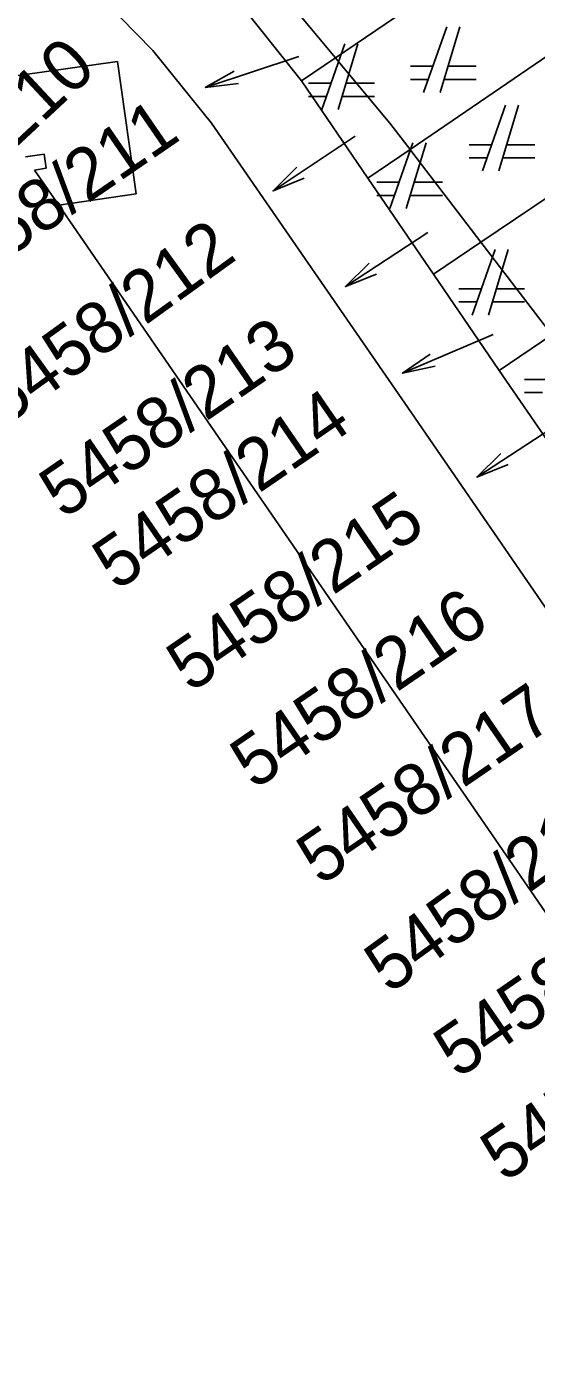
# Model space of a CAD drawing. Extents: x -263587 to -261993, y -1238795 to -1236748.
# Drawn here: x -262822.15 to -262811.29, y -1237202.79 to -1237174.42 of the extents above; entities that cross this region are included whole.
import ezdxf

# ---------------------------------------------------------------- set-up
doc = ezdxf.new("R2010")
doc.units = 0
doc.layers.add('Vrstva 1', color=7, linetype='Continuous')

msp = doc.modelspace()

# ---------------------------------------------------------------- linework, layer by layer
at = {"layer": 'Vrstva 1'}
for p, q in [((-262812.15, -1237172.77), (-262815.57, -1237175.09)), ((-262815.57, -1237175.09), (-262812.15, -1237172.77)), ((-262815.57, -1237175.09), (-262817.11, -1237173.24)), ((-262817.11, -1237173.24), (-262815.57, -1237175.09)), ((-262817.79, -1237173.7), (-262816.29, -1237175.58)), ((-262816.29, -1237175.58), (-262817.79, -1237173.7)), ((-262819.46, -1237174.93), (-262820.51, -1237173.86)), ((-262820.51, -1237173.86), (-262819.46, -1237174.93)), ((-262813.2, -1237174.43), (-262813.69, -1237175.83)), ((-262813.34, -1237175.83), (-262812.92, -1237174.43)), ((-262815.37, -1237174.79), (-262815.86, -1237176.19)), ((-262815.51, -1237176.19), (-262815.09, -1237174.79)), ((-262810.73, -1237174.83), (-262813.98, -1237177.04)), ((-262813.98, -1237177.04), (-262810.73, -1237174.83)), ((-262818.21, -1237176.48), (-262819.46, -1237174.93)), ((-262819.46, -1237174.93), (-262818.21, -1237176.48)), ((-262816.29, -1237175.58), (-262815.57, -1237175.09)), ((-262815.57, -1237175.09), (-262816.29, -1237175.58)), ((-262815.52, -1237175.15), (-262815.57, -1237175.09)), ((-262815.57, -1237175.09), (-262815.52, -1237175.15)), ((-262823.26, -1237175.6), (-262820.21, -1237175.17)), ((-262820.21, -1237175.17), (-262823.26, -1237175.6)), ((-262820.21, -1237175.17), (-262819.81, -1237177.99)), ((-262819.81, -1237177.99), (-262820.21, -1237175.17)), ((-262814.41, -1237176.48), (-262815.52, -1237175.15)), ((-262815.52, -1237175.15), (-262814.41, -1237176.48)), ((-262813.494, -1237175.27), (-262813.97, -1237175.27)), ((-262812.57, -1237175.27), (-262813.172, -1237175.27)), ((-262817.634, -1237175.636), (-262818.342, -1237175.725)), ((-262816.29, -1237175.58), (-262814.88, -1237177.65)), ((-262814.88, -1237177.65), (-262816.29, -1237175.58)), ((-262815.664, -1237175.63), (-262816.14, -1237175.63)), ((-262814.74, -1237175.63), (-262815.342, -1237175.63)), ((-262813.97, -1237175.55), (-262813.592, -1237175.55)), ((-262813.256, -1237175.55), (-262812.57, -1237175.55)), ((-262816.14, -1237175.91), (-262815.762, -1237175.91)), ((-262815.426, -1237175.91), (-262814.74, -1237175.91)), ((-262811.95, -1237176.1), (-262812.44, -1237177.5)), ((-262812.09, -1237177.5), (-262811.67, -1237176.1)), ((-262813.95, -1237182.65), (-262818.21, -1237176.48)), ((-262818.21, -1237176.48), (-262813.95, -1237182.65)), ((-262813.98, -1237177.04), (-262814.41, -1237176.48)), ((-262814.41, -1237176.48), (-262813.98, -1237177.04)), ((-262814.88, -1237177.65), (-262813.98, -1237177.04)), ((-262813.98, -1237177.04), (-262814.88, -1237177.65)), ((-262813.92, -1237176.9), (-262814.41, -1237178.3)), ((-262814.06, -1237178.3), (-262813.64, -1237176.9)), ((-262813.94, -1237177.09), (-262813.98, -1237177.04)), ((-262813.98, -1237177.04), (-262813.94, -1237177.09)), ((-262812.47, -1237179.02), (-262813.94, -1237177.09)), ((-262813.94, -1237177.09), (-262812.47, -1237179.02)), ((-262812.244, -1237176.94), (-262812.72, -1237176.94)), ((-262809.32, -1237176.88), (-262812.47, -1237179.02)), ((-262812.47, -1237179.02), (-262809.32, -1237176.88)), ((-262811.32, -1237176.94), (-262811.922, -1237176.94)), ((-262822.17, -1237177.2), (-262821.77, -1237177.14)), ((-262821.77, -1237177.14), (-262821.73, -1237177.44)), ((-262812.72, -1237177.22), (-262812.342, -1237177.22)), ((-262812.006, -1237177.22), (-262811.32, -1237177.22)), ((-262821.73, -1237177.44), (-262821.98, -1237177.48)), ((-262821.98, -1237177.48), (-262821.46, -1237178.23)), ((-262816.237, -1237177.653), (-262816.897, -1237177.925)), ((-262814.88, -1237177.65), (-262813.48, -1237179.7)), ((-262813.48, -1237179.7), (-262814.88, -1237177.65)), ((-262814.214, -1237177.74), (-262814.69, -1237177.74)), ((-262813.29, -1237177.74), (-262813.892, -1237177.74)), ((-262819.81, -1237177.99), (-262821.46, -1237178.23)), ((-262821.46, -1237178.23), (-262819.81, -1237177.99)), ((-262821.46, -1237178.23), (-262797.76, -1237212.68)), ((-262797.76, -1237212.68), (-262821.46, -1237178.23)), ((-262814.69, -1237178.02), (-262814.312, -1237178.02)), ((-262813.976, -1237178.02), (-262813.29, -1237178.02)), ((-262813.48, -1237179.7), (-262812.47, -1237179.02)), ((-262812.47, -1237179.02), (-262813.48, -1237179.7)), ((-262812.42, -1237179.08), (-262812.47, -1237179.02)), ((-262812.47, -1237179.02), (-262812.42, -1237179.08)), ((-262810.96, -1237180.99), (-262812.42, -1237179.08)), ((-262812.42, -1237179.08), (-262810.96, -1237180.99)), ((-262812.17, -1237179.17), (-262812.66, -1237180.57)), ((-262812.31, -1237180.57), (-262811.89, -1237179.17)), ((-262814.693, -1237179.696), (-262815.355, -1237179.963)), ((-262813.48, -1237179.7), (-262812.08, -1237181.75)), ((-262812.08, -1237181.75), (-262813.48, -1237179.7)), ((-262812.464, -1237180.01), (-262812.94, -1237180.01)), ((-262811.54, -1237180.01), (-262812.142, -1237180.01)), ((-262812.94, -1237180.29), (-262812.562, -1237180.29)), ((-262812.226, -1237180.29), (-262811.54, -1237180.29)), ((-262812.08, -1237181.75), (-262810.96, -1237180.99)), ((-262810.96, -1237180.99), (-262812.08, -1237181.75)), ((-262813.442, -1237181.659), (-262814.141, -1237181.806)), ((-262812.08, -1237181.75), (-262810.67, -1237183.8)), ((-262810.67, -1237183.8), (-262812.08, -1237181.75)), ((-262811.064, -1237181.94), (-262811.54, -1237181.94)), ((-262811.54, -1237182.22), (-262811.162, -1237182.22)), ((-262808, -1237191.31), (-262813.95, -1237182.65)), ((-262813.95, -1237182.65), (-262808, -1237191.31)), ((-262811.893, -1237183.756), (-262812.555, -1237184.023))]:
    msp.add_line(p, q, dxfattribs=at)
for points in [[(-262816.35, -1237175.06), (-262818.342, -1237175.725), (-262817.722, -1237175.371)], [(-262815.15, -1237176.76), (-262816.897, -1237177.925), (-262816.392, -1237177.42)], [(-262813.6, -1237178.81), (-262815.355, -1237179.963), (-262814.847, -1237179.462)], [(-262812.21, -1237180.98), (-262814.141, -1237181.806), (-262813.552, -1237181.402)], [(-262810.8, -1237182.87), (-262812.555, -1237184.023), (-262812.047, -1237183.522)]]:
    msp.add_lwpolyline(points, dxfattribs=at)

# ---------------------------------------------------------------- texts
for s, rotation, p in [('5458/210', 42.9718, (-262825.108, -1237179.555)), ('5458/211', 34.4921, (-262823.887, -1237180.287)), ('5458/212', 35.8099, (-262822.607, -1237182.952)), ('5458/213', 34.4921, (-262821.365, -1237184.931)), ('5458/214', 34.4921, (-262820.235, -1237186.461)), ('5458/215', 34.4921, (-262818.655, -1237188.631)), ('5458/216', 34.4921, (-262817.3, -1237190.698)), ('5458/217', 34.4921, (-262815.885, -1237192.741)), ('5458/218', 35.9817, (-262814.419, -1237195.048)), ('5458/219', 34.4921, (-262812.968, -1237196.853)), ('5458/220', 34.4921, (-262811.971, -1237199.064))]:
    msp.add_text(s, height=1.1, rotation=rotation, dxfattribs=at).set_placement(p)

doc.saveas('drawing.dxf')
